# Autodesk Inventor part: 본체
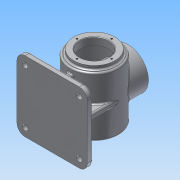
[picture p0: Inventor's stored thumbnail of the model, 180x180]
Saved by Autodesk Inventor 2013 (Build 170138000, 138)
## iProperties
Created: 2015-07
Part Number: 본체
Material: 알루미늄 6061
Document SubType Name: Modeling
Designer: Administrator
Density: 2.71 g/cm^3
Mass: 1277.56 g
Surface Area: 1267.26 cm^2
Volume: 471.426 cm^3
Author: Administrator
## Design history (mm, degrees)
sketch "스케치1"
  geometry: C1 r 45 at (0, 0); 1 further point
  constraints: 1 centre point, 1 coincident
  dimensions: "d0" = 90 diameter of C1
extrude "돌출1" new body sketch "스케치1" stored distance "d1" = 110; taper "d2" = 0 deg
sketch "스케치2"
  geometry: L1 (-65, -68)-(65, -68); L2 (65, -68)-(65, -78); L3 (65, -78)-(-65, -78); L4 (-65, -78)-(-65, -68); 2 further points
  constraints: 8 end point, 2 parallel, 1 horizontal, 1 midpoint, 1 perpendicular, 1 vertical alignment
  dimensions: "d3" = 130 distance of L2.end L3.end; "d5" = 10 distance of L1.end L2.end; "d6" = 78 distance from line of L3 point (0, 0)
extrude "돌출2" join sketch "스케치2" stored distance "d7" = 130; taper "d8" = 0 deg
sketch "스케치3"
  geometry: L1 (130, 0)-(130, 130) reference; L2 (0, 130)-(130, 130) reference; L3 (60, 70)-(60, 110); L4 (60, 110)-(70, 110); L5 (70, 110)-(70, 70); L6 (70, 70)-(110, 70); L7 (110, 70)-(110, 60); L8 (110, 60)-(70, 60); L9 (70, 60)-(70, 20); L10 (70, 20)-(60, 20); L11 (60, 20)-(60, 60); L12 (60, 60)-(20, 60); L13 (20, 60)-(20, 70); L14 (20, 70)-(60, 70); L15 (0, 130)-(130, 130) reference; L16 (130, 130)-(130, 0) reference; L17 (130, 0)-(0, 0) reference; L18 (0, 0)-(0, 130) reference; C1 r 7.5 at (15, 115); C2 r 7.5 at (115, 115); C3 r 7.5 at (15, 15); C4 r 7.5 at (115, 15); 3 further points
  constraints: 24 end point, 8 parallel, 5 equal length, 4 centre point, 3 horizontal alignment, 3 perpendicular, 3 vertical alignment, 2 collinear, 2 midpoint
  dimensions: "d9" = 10 distance of L3.end L4.end; "d11" = 10 distance of L6.end L7.end; "d12" = 90 distance between parallel lines of L10 L4; "d13" = 90 distance between parallel lines of L7 L13; "d14" = 15 diameter of C1; "d15" = 15 diameter of C2; "d16" = 15 diameter of C3; "d17" = 15 diameter of C4; "d18" = 100 distance of C2.centre C1.centre; "d19" = 100 distance of C4.centre C2.centre; "d20" = 15 distance from line of L1 C2.centre; "d21" = 15 distance from line of L15 C2.centre
  node "절단 모서리 투영1"
extrude "돌출3" join sketch "스케치3" stored distance "d22" = 130; taper "d23" = 0 deg
extrude "돌출4" join sketch "스케치3" distance "d24" = 3; taper "d25" = 0 deg
hole "구멍1" diameter "d28" = 10; stored, may be unused: countersink angle "d32" = 90 deg, drill point angle "d34" = 118 deg; dims "d26" = 10, "d27" = 10, "d29" = 6, "d30" = 4, "d31" = 2, "d33" = 8
hole "구멍2" diameter "d37" = 10; stored, may be unused: countersink angle "d41" = 90 deg, drill point angle "d43" = 118 deg; dims "d35" = 10, "d36" = 10, "d38" = 6, "d39" = 4, "d40" = 2, "d42" = 8
hole "구멍3" diameter "d46" = 10; stored, may be unused: countersink angle "d50" = 90 deg, drill point angle "d52" = 118 deg; dims "d44" = 10, "d45" = 10, "d47" = 6, "d48" = 4, "d49" = 2, "d51" = 8
hole "구멍4" diameter "d55" = 10; stored, may be unused: countersink angle "d59" = 90 deg, drill point angle "d61" = 118 deg; dims "d53" = 10, "d54" = 10, "d56" = 6, "d57" = 4, "d58" = 2, "d60" = 8
sketch "스케치4"
  geometry: C1 r 45 at (0, 0) reference; C2 r 38 at (0, 0)
  constraints: 1 centre point, 1 coincident
  dimensions: "d62" = 76 diameter of C2
extrude "돌출5" join sketch "스케치4" distance "d63" = 7; taper "d64" = 0 deg
node "작업 평면1"
sketch "스케치5"
  geometry: L1 (-45, -55)-(45, -55) reference; C1 r 38 at (0, 0); 1 further point
  constraints: 1 centre point, 1 coincident
  dimensions: "d66" = 76 diameter of C1
extrude "돌출6" join sketch "스케치5" stored distance "d67" = 7; taper "d68" = 0 deg
sketch "스케치6"
  geometry: C1 r 38 at (0, 0) reference; C2 r 27 at (0, 0)
  constraints: 1 centre point, 1 coincident
  dimensions: "d69" = 54 diameter of C2
extrude "돌출7" cut sketch "스케치6" distance "d70" = 14; taper "d71" = 0 deg
sketch "스케치7"
  geometry: C1 r 27 at (0, 0) reference; C2 r 40 at (0, 0)
  constraints: 1 centre point, 1 coincident
  dimensions: "d72" = 80 diameter of C2
extrude "돌출8" cut sketch "스케치7" distance "d73" = 96; taper "d74" = 0 deg
sketch "스케치8"
  geometry: C1 r 38 at (0, 0) reference; C2 r 27 at (0, 0)
  constraints: 1 centre point, 1 coincident
  dimensions: "d75" = 54 diameter of C2
extrude "돌출9" cut sketch "스케치8" stored distance "d76" = 96; taper "d77" = 0 deg
sketch "스케치9"
  geometry: C1 r 27 at (0, 0) reference; C2 r 38 at (0, 0) reference; A1 r 32 centre (0, 0) between (0, 32) and (0, 32); 4 further points
  constraints: 6 point on circle, 4 vertical alignment, 2 horizontal alignment, 1 centre point, 1 coincident
  dimensions: "d78" = 64 diameter of A1
hole "구멍5" sketch "스케치9" at (0, 32), (0, -32), (-32, 0), (32, 0) diameter "d79" = 3.242; stored, may be unused: countersink angle "d83" = 90 deg, drill point angle "d85" = 118 deg; dims "d80" = 8, "d81" = 4, "d82" = 2, "d84" = 10
sketch "스케치10"
  geometry: C1 r 27 at (0, 0) reference; C2 r 38 at (0, 0) reference; A1 r 32 centre (0, 0) between (0, 32) and (-32, 0); 2 further points
  constraints: 4 point on circle, 2 horizontal alignment, 2 vertical alignment, 1 centre point, 1 coincident
  dimensions: "d86" = 64 diameter of A1
hole "구멍6" sketch "스케치10" at (0, 32), (-32, 0), (0, -32), (32, 0) diameter "d87" = 3.242; stored, may be unused: countersink angle "d91" = 90 deg, drill point angle "d93" = 118 deg; dims "d88" = 8, "d89" = 4, "d90" = 2, "d92" = 10
fillet "모깎기1" dims "d94" = 3
fillet "모깎기2" dims "d95" = 3
fillet "모깎기3" dims "d96" = 3
fillet "모깎기4" dims "d97" = 3
fillet "모깎기5" dims "d98" = 3
fillet "모깎기6" dims "d99" = 3
fillet "모깎기7" dims "d100" = 3
fillet "모깎기8" dims "d101" = 3
fillet "모깎기9" dims "d102" = 3
fillet "모깎기10" dims "d103" = 3
fillet "모깎기11" dims "d104" = 3
fillet "모깎기12" dims "d105" = 15
fillet "모깎기13" dims "d106" = 3
chamfer "모따기1" distance "d107" = 1; stored, may be unused: second distance "d108" = 2, angle "d109" = 45 deg
sketch "스케치11"
  geometry: C1 r 42 at (0, 0) reference; 1 further point
  constraints: 1 coincident, 1 other
feature "엠보싱1" sketch "스케치11" dims "d0" = 90, "d9" = 10, "d11" = 10, "d12" = 90, "d13" = 90, "d110" = 0.5, "d111" = 0
node "솔리드1"
other parameters: "d65" = 62
